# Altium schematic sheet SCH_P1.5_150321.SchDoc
size 304 x 241 mm; PageSetup: Record=PageOptions¦CenterHorizontal=True¦CenterVertical=True¦PrintScale=0.88¦XCorrection=1.00¦YCorrection=1.00¦PrintKind=2¦BorderSize=5000000¦LeftOffset=0¦BottomOffset=0¦Orientation=2¦PaperLength=1000¦PaperWidth=1000¦Scale=100¦PaperSource=7¦PrintQuality=-3¦MediaType=1¦DitherType=10¦PrintScaleMode=1¦PaperKind=Letter¦PaperIndex=1
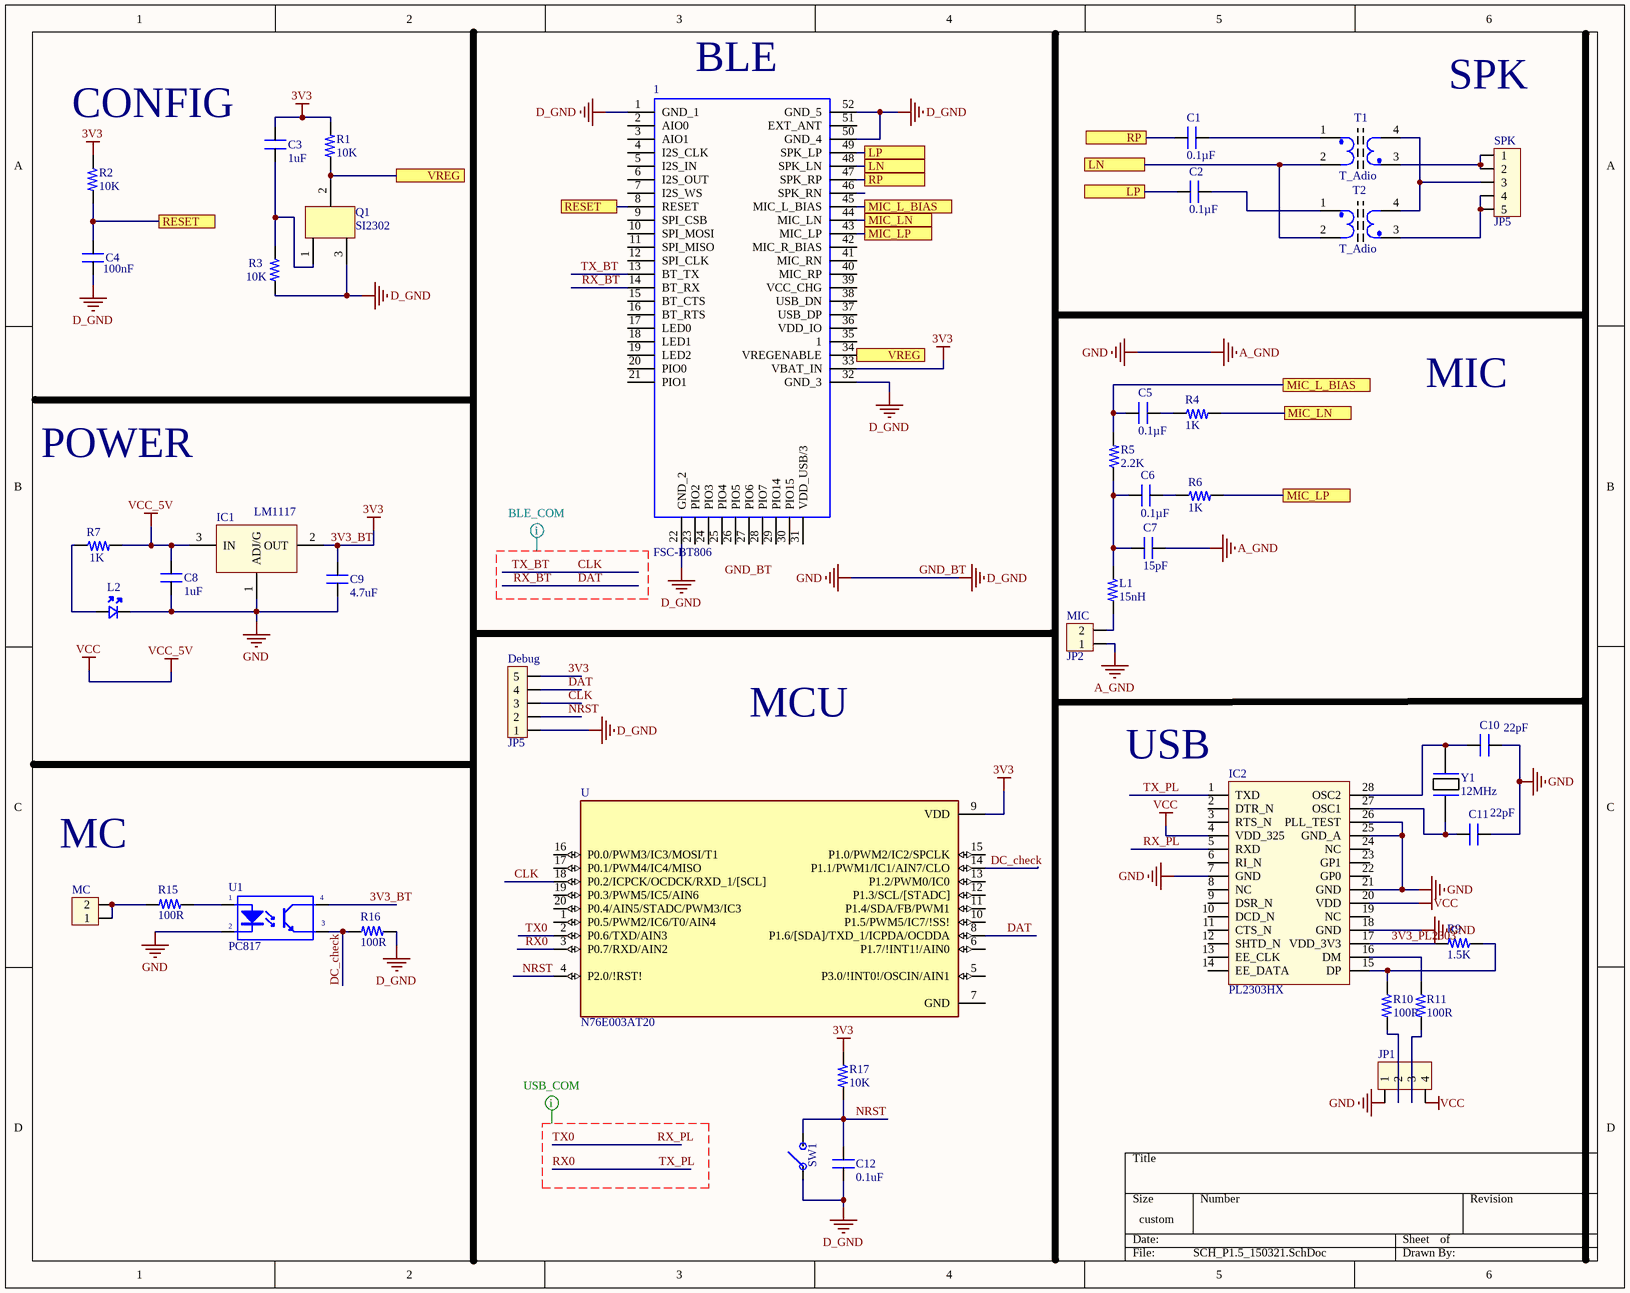
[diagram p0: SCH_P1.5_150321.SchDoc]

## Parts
1  FSC-BT806  [FSCBT806]
C1  0.1µF  [CAP_0805]
C2  0.1µF  [CAP_0805]
C3  1uF  [CAP_0805]
C4  100nF  [CAP_0805]
C5  0.1µF  [CAP_0805]
C6  0.1µF  [CAP_0805]
C7  15pF  [CAP_0805]
C8  1uF  [CAP_0805]
C9  4.7uF  [CAP_0805]
C10  22pF  [CAP_0805]
C11  22pF  [CAP_0805]
C12  0.1uF  [CAP_0805]
Debug  JP5  [JP5]
IC1  LM1117  [SOT223-4N]
IC2  PL2303HX  [PL2303]
JP1  (no value)  [CON4]
L1  15nH  [RES_0805]
L2  (no value)  [LED_0805]
MC  (no value)  [CON2]
MIC  JP2  [CON2]
Q1  SI2302  [SOT23A]
R1  10K  [RES_0805]
R2  10K  [RES_0805]
R3  10K  [RES_0805]
R4  1K  [RES_0805]
R5  2.2K  [RES_0805]
R6  1K  [RES_0805]
R7  1K  [RES_0805]
R9  1.5K  [RES_0805]
R10  100R  [RES_0805]
R11  100R  [RES_0805]
R15  100R  [RES_0805]
R16  100R  [RES_0805]
R17  10K  [RES_0805]
SPK  JP5  [CON5]
SW1  (no value)  [SW_342_SMD]
T1  T_Adio  [T_Adito]
T2  T_Adio  [T_Adito]
U  N76E003AT20  [SOP65P640X120-20N]
U1  PC817  [DIP4/W0.3]
Y1  12MHz  [XTAL_314_240X47_SMD]

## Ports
LN, LP, MIC_L_BIAS, MIC_LN, MIC_LP, RESET, RP, VREG

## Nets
3V3: 1.33(VBAT_IN) C3.2 C9.2 Debug.5 IC1.2(OUT) R1.2 R2.2 R17.2 U.9(VDD) U1.4(C)  [also labelled 3V3_BT]
GND_BT: 1.1(GND_1) 1.22(GND_2) 1.32(GND_3) 1.50(GND_4) 1.52(GND_5) C4.1 C7.2 C8.1 C9.1 C10.2 C11.1 C12.1 Debug.1 IC1.1(ADJ/G) IC2.7(GND) IC2.18(GND) IC2.21(GND) IC2.25(GND_A) IC2.26(PLL_TEST) JP1.1 L2.K MIC.1 Q1.3 R3.1 R16.2 SW1.1 U1.2(K)  [also labelled A_GND, D_GND, GND]
VCC: C8.2 IC1.3(IN) IC2.4(VDD_325) IC2.20(VDD) JP1.4 R7.1  [also labelled VCC_5V]
3V3_PL2303: IC2.17(VDD_3V3) R9.1
CLK: 1.13(BT_TX) Debug.3 U.18(P0.2/ICPCK/OCDCK/RXD_1/[SCL])  [also labelled TX_BT]
DAT: 1.14(BT_RX) Debug.4 U.8(P1.6/[SDA]/TXD_1/ICPDA/OCDDA)  [also labelled RX_BT]
DC_check: R16.1 U.14(P1.1/PWM1/IC1/AIN7/CLO) U1.3(E)
LN: 1.48(SPK_LN) T1.2 T2.2 ; port LN
LP: 1.49(SPK_LP) C2.1 ; port LP
MIC_L_BIAS: 1.45(MIC_L_BIAS) C5.1 R5.1 ; port MIC_L_BIAS
MIC_LN: 1.44(MIC_LN) R4.1 ; port MIC_LN
MIC_LP: 1.43(MIC_LP) R6.1 ; port MIC_LP
NRST: C12.2 Debug.2 R17.1 SW1.2 U.4(P2.0/!RST!)
RESET: 1.8(RESET) C4.2 R2.1 ; port RESET
RP: 1.47(SPK_RP) C1.1 ; port RP
RX0: IC2.1(TXD) U.3(P0.7/RXD/AIN2)  [also labelled TX_PL]
RX_PL: IC2.5(RXD) U.2(P0.6/TXD/AIN3)  [also labelled TX0]
VREG: 1.34(VREGENABLE) Q1.2 R1.1 ; port VREG
NetC1_2: C1.2 T1.1
NetC2_2: C2.2 T2.1
NetC3_1: C3.1 Q1.1 R3.2
NetC5_2: C5.2 R4.2
NetC6_1: C6.1 C7.1 L1.2 R5.2
NetC6_2: C6.2 R6.2
NetC10_1: C10.1 IC2.28(OSC2) Y1.2
NetC11_2: C11.2 IC2.27(OSC1) Y1.1
NetIC2_15: IC2.15(DP) R9.2 R10.2
NetIC2_16: IC2.16(DM) R11.2
NetJP1_2: JP1.2 R10.1
NetJP1_3: JP1.3 R11.1
NetL1_1: L1.1 MIC.2
NetL2_A: L2.A R7.2
NetMC_1: MC.1 MC.2 R15.1
NetR15_2: R15.2 U1.1(A)
NetSPK_1: SPK.1 SPK.2 T1.3
NetSPK_3: SPK.3 T1.4 T2.4
NetSPK_4: SPK.4 SPK.5 T2.3

Not connected (* = marked no-connect by the designer): 1 2(AIO0) 3(AIO1) 4(I2S_CLK) 5(I2S_IN) 6(I2S_OUT) 7(I2S_WS) 9(SPI_CSB) 10(SPI_MOSI) 11(SPI_MISO) 12(SPI_CLK) 15(BT_CTS) 16(BT_RTS) 17(LED0) 18(LED1) 19(LED2) 20(PIO0) 21(PIO1) 23(PIO2) 24(PIO3) 25(PIO4) 26(PIO5) 27(PIO6) 28(PIO7) 29(PIO14) 30(PIO15) 31(VDD_USB/3) 35(1) 36(VDD_IO) 37(USB_DP) 38(USB_DN) 39(VCC_CHG) 40(MIC_RP) 41(MIC_RN) 42(MIC_R_BIAS) 46(SPK_RN) 51(EXT_ANT); IC2 2(DTR_N) 3(RTS_N) 6(RI_N) 8(NC) 9(DSR_N) 10(DCD_N) 11(CTS_N) 12(SHTD_N) 13(EE_CLK) 14(EE_DATA) 19(NC) 22(GP0) 23(GP1) 24(NC); U 1(P0.5/PWM2/IC6/T0/AIN4) 5(P3.0/!INT0!/OSCIN/AIN1) 6(P1.7/!INT1!/AIN0) 7(GND) 10(P1.5/PWM5/IC7/!SS!) 11(P1.4/SDA/FB/PWM1) 12(P1.3/SCL/[STADC]) 13(P1.2/PWM0/IC0) 15(P1.0/PWM2/IC2/SPCLK) 16(P0.0/PWM3/IC3/MOSI/T1) 17(P0.1/PWM4/IC4/MISO) 19(P0.3/PWM5/IC5/AIN6) 20(P0.4/AIN5/STADC/PWM3/IC3)

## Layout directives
net class Undefined: CLK, DAT, RX0, RX_BT, RX_PL, TX0, TX_BT, TX_PL

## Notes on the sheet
- (near 1) BLE
- SPK
- (near R2) CONFIG
- MIC
- POWER
- MCU
- (near IC2) USB
- MC
- Labels drawn without touching a wire or pin: GND_BT

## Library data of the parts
C1 C2 C5-C7 C12 = CAP_0.1uF-50V-5%-0805: 0.1µF ±5% 50V Ceramic Capacitor X7R 0805 (2012 Metric); Manufacturer: KEMET; Manufacturing Part Number: C0805C104J5RACTU
C3 C8 = CAP_1uF-50V-5%-0805: 1µF ±5% 50V Ceramic Capacitor X7R 0805 (2012 Metric); Manufacturer: Yageo; Manufacturing Part Number: CC0805JKX7R9BB105
C4 = CAP_1uF-50V-5%-0805: 100µF ±5% 50V Ceramic Capacitor X7R 0805 (2012 Metric); Manufacturer: Yageo; Manufacturing Part Number: CC0805JKX7R9BB105
C9 = CAP_1uF-50V-5%-0805: 4.7µF ±5% 50V Ceramic Capacitor X7R 0805 (2012 Metric); Manufacturer: Yageo; Manufacturing Part Number: CC0805JKX7R9BB105
C10 C11 = CAP_22pF-50V-5%-0805: 22pF ±5% 50V Ceramic Capacitor C0G, NP0 0805 (2012 Metric); Manufacturer: KEMET; Manufacturer Part Number: C0805C220J5GACTU
IC1 = LM1117: Available in 1.8V, 2.5V, 2.85V, 3.3V, 5V, and  Adjustable Versions; Value: LM317
IC2 = PL2303HX: USB - RS232 Converter; Value: PL2303
JP1 = Con4: Connector 4
L1 = RES_1K-0.125W-1%-0805: Conductor 15nH; Manufacturer: 垈㎵á; Manufacturer Part Number: RC0805FR-071KL
L2 = LED-RED_10mA-0805: Red 621nm LED Indication - Discrete 2V 0805 (2012 Metric); Manufacturer: Lite-On Inc.; Manufacturer Part Number: LTST-C170EKT
MC MIC = Con2: Connector 2
Q1 = DV3
R1-R4 R6 = RES_10K-0.125W-1%-0805_1: 10 kOhms ±1% 0.125W, 1/8W Chip Resistor 0805 (2012 Metric) Moisture Resistant Thick Film; Manufacturer: Yageo; Manufacturing Part Number: RC0805FR-0710KL
R5 = RES_10K-0.125W-1%-0805_1: 2.2kOhms ±1% 0.125W, 1/8W Chip Resistor 0805 (2012 Metric) Moisture Resistant Thick Film; Manufacturer: Yageo; Manufacturing Part Number: RC0805FR-0710KL
R7 = RES_10K-0.125W-1%-0805_1: 1 kOhms ±1% 0.125W, 1/8W Chip Resistor 0805 (2012 Metric) Moisture Resistant Thick Film; Manufacturer: Yageo; Manufacturing Part Number: RC0805FR-0710KL
R9 = RES_1.5K-0.125W-1%-0805: 1.5 kOhms ±1% 0.125W, 1/8W Chip Resistor 0805 (2012 Metric) Thick Film; Manufacturer: TE Connectivity Passive Product; Manufacturing Part Number: CRG0805F1K5
R10 R11 = RES_0ohm-0.125W-1%-0805_1: 1000Ohms ±1% 0.125W, 1/8W Chip Resistor 0805 (2012 Metric) Moisture Resistant Thick Film; Manufacturer: 垈㎵á; Manufacturer Part Number: RC0805FR-071KL
R15 R16 = RES_1K-0.125W-1%-0805: 1 kOhms ±1% 0.125W, 1/8W Chip Resistor 0805 (2012 Metric) Moisture Resistant Thick Film; Manufacturer: 垈㎵á; Manufacturer Part Number: RC0805FR-071KL
R17 = RES_10MOHM-0.125W-1%-0805: 10K ±1% 0.125W, 1/8W Chip Resistor 0805 (2012 Metric) Automotive AEC-Q200, High Voltage Thick Film; Manufacturer: Rohm Semiconductor; Manufacturing Part Number: KTR10EZPF1005
SPK = Con5: Connector 5
SW1 = SW_KSR223GLFG-SMD: Tactile Switch SPST-NO Top Actuated Surface Mount; Manufacturer: C&K
T1 T2 = T_Adio: Transformer Audio; Designed by: VanDungEvn; Value: BAX
U = N76E003AT20: 8051 N76 Microcontroller IC 8-Bit 16MHz 18KB _18K x 8_ FLASH 20-TSSOP; MF: Nuvoton Technology
U1 = PC817: Single Opto
Y1 = XTAL_8MHZ-LFXTAL030234: Crystals 8MHz 22pF -20C 70C; Manufacturer: IQD Frequency Products; Manufacturing Part Number: LFXTAL030234Reel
